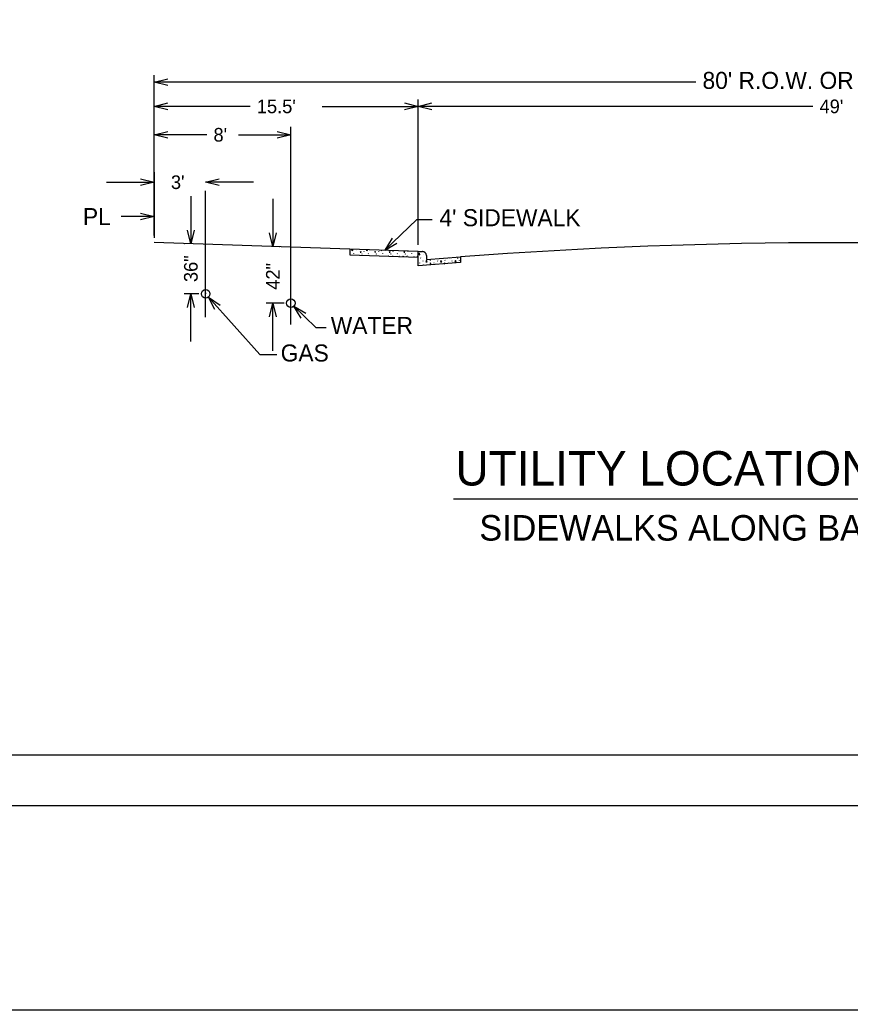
# Model space of a CAD drawing. Extents: x 524397 to 525117, y 3701341 to 3701821.
# Drawn here: x 524706.5 to 524804, y 3701341 to 3701457.3 of the extents above; entities that cross this region are included whole.
import ezdxf

# ---------------------------------------------------------------- set-up
doc = ezdxf.new("R2010")
doc.units = 0
for name, color, linetype in [('Level 1', 7, 'Continuous'), ('Level 11', 7, 'Continuous'), ('Level 9', 7, 'Continuous'), ('Pam batch print border', 7, 'Continuous')]:
    doc.layers.add(name, color=color, linetype=linetype)

msp = doc.modelspace()

# ---------------------------------------------------------------- linework, layer by layer
at = {"layer": 'Level 1'}
for p, q in [((524757.47, 3701401.06), (524847.19, 3701401.06)), ((524442.4, 3701370.98), (525097.4, 3701370.98))]:
    msp.add_line(p, q, dxfattribs=at)
at = {"layer": 'Level 11'}
for p, q in [((524722.31, 3701431.98), (524722.31, 3701450.81)), ((524722.31, 3701450.01), (524723.91, 3701450.41)), ((524785.89, 3701450.01), (524722.31, 3701450.01)), ((524723.91, 3701449.61), (524722.31, 3701450.01)), ((524722.31, 3701431.98), (524722.31, 3701447.96)), ((524722.31, 3701447.16), (524723.91, 3701447.56)), ((524733.56, 3701447.16), (524722.31, 3701447.16)), ((524723.91, 3701446.76), (524722.31, 3701447.16)), ((524742.04, 3701447.16), (524753.29, 3701447.16)), ((524751.69, 3701447.56), (524753.29, 3701447.16)), ((524753.29, 3701447.16), (524751.69, 3701446.76)), ((524753.29, 3701430.9), (524753.29, 3701447.96)), ((524753.29, 3701447.16), (524754.89, 3701447.56)), ((524799.63, 3701447.16), (524753.29, 3701447.16)), ((524754.89, 3701446.76), (524753.29, 3701447.16)), ((524738.35, 3701421.53), (524738.35, 3701444.75)), ((524722.31, 3701443.82), (524723.91, 3701444.22)), ((524728.47, 3701443.82), (524722.31, 3701443.82)), ((524723.91, 3701443.42), (524722.31, 3701443.82)), ((524732.19, 3701443.82), (524738.35, 3701443.82)), ((524736.75, 3701444.22), (524738.35, 3701443.82)), ((524738.35, 3701443.82), (524736.75, 3701443.42)), ((524722.35, 3701431.7), (524722.35, 3701439.44)), ((524716.7, 3701438.25), (524722.31, 3701438.25)), ((524720.71, 3701438.65), (524722.31, 3701438.25)), ((524722.31, 3701438.25), (524720.71, 3701437.85)), ((524728.35, 3701438.25), (524729.95, 3701438.65)), ((524733.95, 3701438.25), (524728.35, 3701438.25)), ((524729.95, 3701437.85), (524728.35, 3701438.25)), ((524726.61, 3701436.63), (524726.61, 3701431.03)), ((524728.35, 3701422.38), (524728.35, 3701437.22)), ((524722.35, 3701431.7), (524722.35, 3701435.89)), ((524736.24, 3701436.3), (524736.24, 3701430.7)), ((524722.31, 3701434.23), (524718.43, 3701434.23)), ((524720.71, 3701434.63), (524722.31, 3701434.23)), ((524722.31, 3701434.23), (524720.71, 3701433.83)), ((524749.38, 3701430.26), (524753.16, 3701433.88)), ((524753.16, 3701433.88), (524754.96, 3701433.88)), ((524726.61, 3701431.03), (524726.21, 3701432.63)), ((524727.01, 3701432.63), (524726.61, 3701431.03)), ((524736.24, 3701430.7), (524735.84, 3701432.3)), ((524736.64, 3701432.3), (524736.24, 3701430.7)), ((524753.29, 3701430.1), (524722.31, 3701431.18)), ((524725.85, 3701431.03), (524725.81, 3701431.03)), ((524737.02, 3701430.7), (524737.04, 3701430.7)), ((524750.26, 3701431.66), (524749.38, 3701430.26)), ((524749.38, 3701430.26), (524750.81, 3701431.08)), ((524745.29, 3701430.38), (524745.27, 3701429.72)), ((524745.27, 3701429.72), (524753.29, 3701429.44)), ((524753.29, 3701430.1), (524745.29, 3701430.38)), ((524745.76, 3701429.83), (524745.74, 3701429.87)), ((524746.08, 3701430.25), (524746.07, 3701430.28)), ((524746.68, 3701429.83), (524746.67, 3701429.8)), ((524746.69, 3701429.83), (524746.68, 3701429.81)), ((524746.94, 3701430.16), (524746.93, 3701430.12)), ((524747.46, 3701429.83), (524747.44, 3701429.87)), ((524747.78, 3701430.25), (524747.77, 3701430.28)), ((524748.38, 3701429.83), (524748.37, 3701429.8)), ((524748.4, 3701429.83), (524748.38, 3701429.81)), ((524748.64, 3701430.16), (524748.63, 3701430.12)), ((524749.16, 3701429.83), (524749.15, 3701429.87)), ((524750.08, 3701429.83), (524750.07, 3701429.8)), ((524750.1, 3701429.83), (524750.08, 3701429.81)), ((524750.31, 3701429.57), (524750.29, 3701429.6)), ((524750.34, 3701430.16), (524750.34, 3701430.12)), ((524750.86, 3701429.83), (524750.85, 3701429.87)), ((524751.14, 3701429.51), (524751.13, 3701429.52)), ((524751.78, 3701429.83), (524751.77, 3701429.8)), ((524751.8, 3701429.83), (524751.78, 3701429.81)), ((524752.01, 3701429.57), (524751.99, 3701429.6)), ((524752.04, 3701430.14), (524752.04, 3701430.12)), ((524752.56, 3701429.83), (524752.55, 3701429.87)), ((524752.85, 3701429.49), (524752.84, 3701429.52)), ((524753.29, 3701428.44), (524753.29, 3701430.1)), ((524753.29, 3701430.1), (524753.8, 3701430.1)), ((524753.29, 3701429.44), (524753.29, 3701430.1)), ((524753.61, 3701429.33), (524753.59, 3701429.36)), ((524753.8, 3701430.1), (524753.79, 3701430.1)), ((524753.93, 3701429.74), (524753.92, 3701429.77)), ((524754.29, 3701429.64), (524754.29, 3701429.17)), ((524754.29, 3701429.17), (524758.29, 3701429.48)), ((524757.01, 3701429.33), (524757, 3701429.36)), ((524758.29, 3701429.48), (524758.29, 3701428.81)), ((524758.29, 3701428.81), (524753.29, 3701428.44)), ((524753.45, 3701428.76), (524753.44, 3701428.73)), ((524753.89, 3701428.98), (524753.88, 3701429.02)), ((524754.75, 3701429.06), (524754.74, 3701429.1)), ((524755.15, 3701428.76), (524755.14, 3701428.73)), ((524755.6, 3701428.98), (524755.58, 3701429.02)), ((524756.23, 3701429.32), (524756.22, 3701429.3)), ((524756.24, 3701429.32), (524756.23, 3701429.31)), ((524756.46, 3701429.06), (524756.44, 3701429.1)), ((524756.85, 3701428.76), (524756.84, 3701428.73)), ((524757.3, 3701428.98), (524757.28, 3701429.02)), ((524757.93, 3701429.32), (524757.92, 3701429.3)), ((524757.95, 3701429.33), (524757.93, 3701429.31)), ((524758.16, 3701429.06), (524758.14, 3701429.1)), ((524727.55, 3701425.13), (524725.81, 3701425.13)), ((524726.21, 3701423.53), (524726.61, 3701425.13)), ((524726.61, 3701419.53), (524726.61, 3701425.13)), ((524726.61, 3701425.13), (524727.01, 3701423.53)), ((524728.35, 3701425.24), (524728.35, 3701425.14)), ((524729.44, 3701423.29), (524728.67, 3701424.75)), ((524728.67, 3701424.75), (524730.04, 3701423.82)), ((524728.67, 3701424.75), (524734.7, 3701418)), ((524737.55, 3701424.05), (524735.44, 3701424.05)), ((524735.84, 3701422.45), (524736.24, 3701424.05)), ((524736.24, 3701418.44), (524736.24, 3701424.05)), ((524736.24, 3701424.05), (524736.64, 3701422.45)), ((524738.35, 3701423.92), (524738.35, 3701424.02)), ((524739.57, 3701422.29), (524738.7, 3701423.69)), ((524738.7, 3701423.69), (524740.13, 3701422.86)), ((524738.7, 3701423.69), (524741.27, 3701421.19)), ((524741.27, 3701421.19), (524742.51, 3701421.19)), ((524734.7, 3701418), (524736.69, 3701418))]:
    msp.add_line(p, q, dxfattribs=at)
for points in [[(524745.58, 3701430.37), (524745.49, 3701430.28), (524745.64, 3701430.21)], [(524745.65, 3701430.21), (524745.63, 3701430.37)], [(524746.61, 3701430.02), (524746.57, 3701430.11), (524746.5, 3701430.05), (524746.61, 3701430.02)], [(524747.22, 3701430.31), (524747.19, 3701430.28), (524747.35, 3701430.21)], [(524747.35, 3701430.21), (524747.34, 3701430.31)], [(524748.31, 3701430.02), (524748.27, 3701430.11), (524748.2, 3701430.05), (524748.31, 3701430.02)], [(524748.96, 3701430.25), (524749.05, 3701430.21)], [(524749.05, 3701430.21), (524749.05, 3701430.25)], [(524749.84, 3701429.56), (524749.83, 3701429.57), (524749.82, 3701429.56)], [(524750.02, 3701430.02), (524749.97, 3701430.11), (524749.9, 3701430.05), (524750.02, 3701430.02)], [(524751.57, 3701429.5), (524751.53, 3701429.57), (524751.5, 3701429.5)], [(524751.72, 3701430.02), (524751.67, 3701430.11), (524751.6, 3701430.05), (524751.72, 3701430.02)], [(524753.29, 3701429.47), (524753.23, 3701429.57), (524753.18, 3701429.44)], [(524753.5, 3701429.7), (524753.47, 3701429.91), (524753.34, 3701429.78), (524753.49, 3701429.7)], [(524753.96, 3701428.49), (524753.96, 3701428.5), (524753.94, 3701428.49)], [(524754.37, 3701428.89), (524754.28, 3701429.07), (524754.2, 3701428.9), (524754.37, 3701428.89)], [(524754.78, 3701428.66), (524754.74, 3701428.75), (524754.67, 3701428.7), (524754.78, 3701428.66)], [(524756.08, 3701428.89), (524755.98, 3701429.07), (524755.91, 3701428.9), (524756.07, 3701428.89)], [(524756.47, 3701428.68), (524756.44, 3701428.75), (524756.37, 3701428.7), (524756.44, 3701428.68)], [(524757.78, 3701428.89), (524757.68, 3701429.07), (524757.61, 3701428.9), (524757.77, 3701428.89)]]:
    msp.add_lwpolyline(points, dxfattribs=at)
for centre in [(524728.35, 3701425.13), (524738.35, 3701424.05)]:
    msp.add_circle(centre, 0.5, dxfattribs=at)
for centre, radius, start, end in [((524802.29, 3700846.7), 584.44, 85.68236, 94.31764), ((524753.79, 3701429.61), 0.494, 3.7079, 90.7668)]:
    msp.add_arc(centre, radius, start, end, dxfattribs=at)
at = {"layer": 'Level 9'}
msp.add_lwpolyline([(524396.79, 3701820.98), (525116.79, 3701820.98), (525116.79, 3701340.98), (524396.79, 3701340.98)], close=True, dxfattribs=at)
at = {"layer": 'Pam batch print border'}
msp.add_lwpolyline([(524433.4, 3701796.98), (525105.4, 3701796.98), (525105.4, 3701364.98), (524433.4, 3701364.98)], close=True, dxfattribs=at)
msp.add_lwpolyline([(524433.4, 3701796.98), (525105.4, 3701796.98), (525105.4, 3701364.98), (524433.4, 3701364.98)], close=True, dxfattribs=at)

# ---------------------------------------------------------------- texts
at = {"layer": 'Level 1'}
msp.add_text('UTILITY LOCATIONS - STREET', height=4.0362, dxfattribs=at).set_placement((524757.68, 3701402.62))
at = {"layer": 'Level 11'}
for s, height, p in [("80' R.O.W. OR LARGER", 2, (524786.69, 3701449.21)), ("49'", 1.601, (524800.43, 3701446.36)), ("15.5'", 1.601, (524734.36, 3701446.36)), ("8'", 1.601, (524729.27, 3701443.02)), ("3'", 1.601, (524724.27, 3701437.45)), ('PL', 2, (524713.94, 3701433.21)), ("4' SIDEWALK", 2, (524755.8, 3701433.08)), ('WATER', 2, (524743.04, 3701420.42)), ('GAS', 2, (524737.16, 3701417.19)), ('SIDEWALKS ALONG BACK-OF-CURB', 3, (524760.49, 3701396.15))]:
    msp.add_text(s, height=height, dxfattribs=at).set_placement(p)
for s, p in [('36"', (524727.41, 3701426.52)), ('42"', (524737.04, 3701425.62))]:
    msp.add_text(s, height=1.601, rotation=90, dxfattribs=at).set_placement(p)

doc.saveas('drawing.dxf')
